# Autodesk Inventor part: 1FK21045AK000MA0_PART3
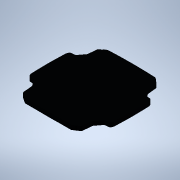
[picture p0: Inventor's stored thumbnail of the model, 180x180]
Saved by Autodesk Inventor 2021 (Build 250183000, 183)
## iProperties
Created: 2025-04
Part Number: 1FK21045AK000MA0_PART3
Material: Generic
Catalog Web Link: www.3dfindit.com
Description: -Servo synchronous motor
Document SubType Name: Modeling
Designer: psAdmin
Mass: 21.7019 g
Surface Area: 120.085 cm^2
Volume: 21.7019 cm^3
Density: 1 g/cm^3
Appearance: PSOLRGB-38-46-56
Category: PARTsolutions
Title: 1FK21045AK000MA0_PART3
Author: Cadenas PARTsolutions
Comments: Servo synchronous motor
Sending System: PARTsolutions
Preprocessor: ST-DEVELOPER v19.3
PSOL_IDENT_0: {$CADENAS_DATA/23d-libs/siemens_ag/_cat_/3d/2f/1fk21045ak000ma0.prj},213 {VTYP=3D},{NB=1FK21045AK000
PSOL_IDENT_1: MA0_PART3},{LINA=1FK21045AK000MA0_PART3},{NN=1FK21045AK000MA0_PART3},{NOPRJ=TRUE},{DATE=19.08.2025 1
PSOL_IDENT_2: 4:00:34},{GEOMDATE=30.07.2025 02:01:24},{VERSION=},{LINEID=10},{WBVAR=},{WBNUMERIC=}  {NB=1FK21045AK
PSOL_IDENT_3: 000MA0_PART3},{LINA=1FK21045AK000MA0_PART3},{KT=DUMMY},{PREVIEW=../../../_pool_/a9/69/p_d211_xx_0081
PSOL_IDENT_4: 8j.png},{DESCSHORT=SIMOTICS S-1FK2 HD, SINAMICS S210 3AC 400V-480V, 1.7 Nm, 6000 rpm},{DESCLONG=SIMO
PSOL_IDENT_5: TICS S-1FK2 HD servo motor M0=2.4 Nm; PN = 1.07 kW at nN=6000 rpm (380-480 V); PN = 0.75 kW at nN=30
PSOL_IDENT_6: 00 rpm (200-240 V); degree of protection IP64; cylindrical shaft D19x40mm; absolute encoder 22-bit +
PSOL_IDENT_7: 12-bit multiturn (encoder AM22DQC); with OCC interface; plug size M17, rotatable; SIMOTICS S-1FK2 s
PSOL_IDENT_8: ervomotorfor a wide range of uses in industrial environments. SIMOTICS S‑1FK2 servomotors are compac
PSOL_IDENT_9: t synchronous motors with a high dynamic performance that set themselves apart as a result of their
PSOL_IDENT_10: high power density, degree of protection and overload capability. The motors are available in two va
PSOL_IDENT_11: riants: as High Dynamic variant (highest dynamic performance as a result of the low intrinsic moment
PSOL_IDENT_12: of inertia for applications demanding a high dynamic performance with low moved masses) - and as Co
PSOL_IDENT_13: mpact variant (precise and stable closed-loop control for medium up to large moved masses as a resul
PSOL_IDENT_14: t of a medium intrinsic moment of inertia). SIMOTICSS‑1FK2 servomotors fully exploit their strengths
PSOL_IDENT_15: in a system with the SINAMICSS210 frequency converter and simple connection using the one cable con
PSOL_IDENT_16: nection (OCC). Advantages include the short control and positioning times, fast and precise correcti
PSOL_IDENT_17: on of disturbing quantities as well as stable control with a high dynamic performance. The servo mot
PSOL_IDENT_18: ors can be configured to address a wide range of requirements. For example with and without holding
PSOL_IDENT_19: brake, IP64 or IP65 degree of protection, singleturn or multiturn absolute encoders - to name just a
PSOL_IDENT_20: few. Further, the servomotors are available in different shaft heights extending from 20 to 100. A
PSOL_IDENT_21: shaft sealing ring is available to achieve an IP65 degree of protection and for subsequent mounting
PSOL_IDENT_22: at the motor or as spare part. SIMOTICS - the optimum motor for each and every motion control applic
PSOL_IDENT_23: ation.},{INTNO=804766789342},{SUPPLIERALTNO=1FK2104-5AK00-0MA0},{MANUID=1FK21045AK000MA0},{MANUNAME=
PSOL_IDENT_24: Siemens},{MANUTYPEDESC=Synchronous motor 1FK2-HD 2,39 Nm},{AAU732=SIMOTICS},{AAO057=S-1FK2},{AAU734=
PSOL_IDENT_25: SIMOTICS S-1FK2 HD servo motor M0=2.4 Nm; PN = 1.07 kW at nN=6000 rpm (380-480 V); PN = 0.75 kW at n
PSOL_IDENT_26: N=3000 rpm (200-240 V); degree of protection IP64; cylindrical shaft D19x40mm; absolute encoder 22-b
PSOL_IDENT_27: it + 12-bit multiturn (encoder AM22DQC); with OCC interface; plug size M17, rotatable;},{AAW338=Sync
PSOL_IDENT_28: hronous motor 1FK2-HD 2,39 Nm},{AAO742=SIMOTICS},{AAO663=4042948691151},{NOCUPEROU=1},{PRICEQUANTITY=
PSOL_IDENT_29: 1},{QUANTITYMIN=1},{QUANTITYINT=1},{CTN=85015100},{COO=DE},{AAO676=1FK2104-5AK00-0MA0},{AAO677=Sieme
PSOL_IDENT_30: ns AG},{ORDERUNIT=C62},{CONTENTUNIT=C62}
NB: 1FK21045AK000MA0_PART3
NT: Servo synchronous motor
NBSYN: $MANUID._PART3
LINA: 1FK21045AK000MA0_PART3
CATALOG: SIEMENS
PREVIEW: ../../../_pool_/a9/69/p_d211_xx_00818j.png
DESCSHORT: SIMOTICS S-1FK2 HD, SINAMICS S210 3AC 400V-480V, 1.7 Nm, 6000 rpm
DESCLONG: SIMOTICS S-1FK2 HD servo motor M0=2.4 Nm; PN = 1.07 kW at nN=6000 rpm (380-480 V); PN = 0.75 kW at nN=3000 rpm (200-240 V); degree of protection IP64; cylindric
INTNO: 804766789342
SUPPLIERALTNO: 1FK2104-5AK00-0MA0
MANUID: 1FK21045AK000MA0
MANUNAME: Siemens
MANUTYPEDESC: Synchronous motor 1FK2-HD 2,39 Nm
AAU732: SIMOTICS
AAO057: S-1FK2
AAU734: SIMOTICS S-1FK2 HD servo motor M0=2.4 Nm; PN = 1.07 kW at nN=6000 rpm (380-480 V); PN = 0.75 kW at nN=3000 rpm (200-240 V); degree of protection IP64; cylindric
AAW338: Synchronous motor 1FK2-HD 2,39 Nm
AAO742: SIMOTICS
AAO663: 4042948691151.0
NOCUPEROU: 1
PRICEQUANTITY: 1
QUANTITYMIN: 1
QUANTITYINT: 1
CTN: 85015100
COO: DE
ARTICLENO: 1FK21045AK000MA0_PART3
BOMINFO: 1FK21045AK000MA0_PART3
CREATOR: CADENAS GmbH
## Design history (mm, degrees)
feature "2025_04_17_15_39_51_0634"
body "Solid1"
